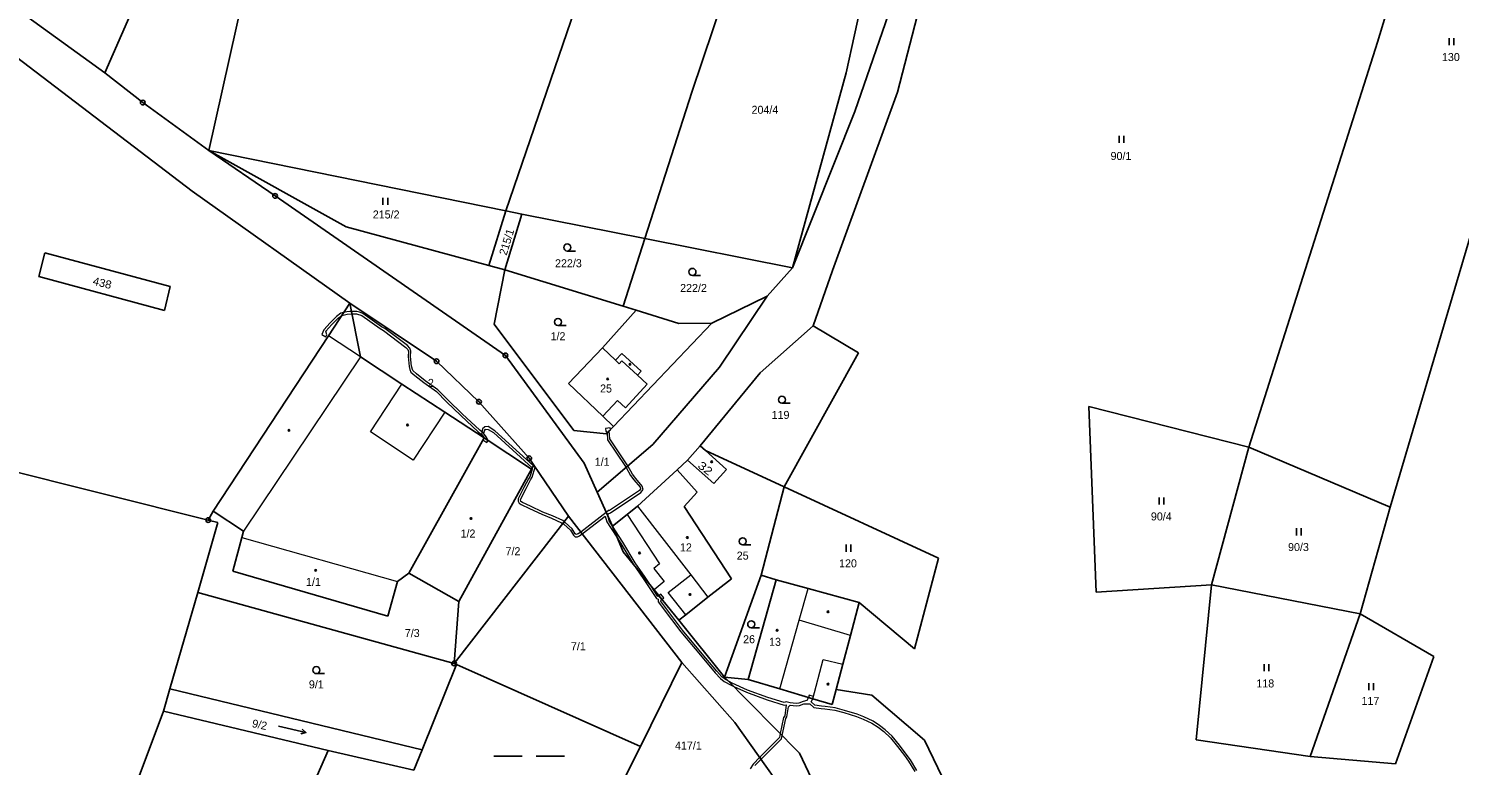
# Model space of a CAD drawing. Extents: x -791548 to -789311, y -1142631 to -1140855.
# Drawn here: x -790444.3 to -790140.3, y -1142115.7 to -1141959 of the extents above; entities that cross this region are included whole.
import ezdxf
from ezdxf.enums import TextEntityAlignment as Align

# ---------------------------------------------------------------- set-up
doc = ezdxf.new("R2010")
doc.units = 0
doc.header["$LTSCALE"] = 0.68
for name, color, linetype, lineweight in [('1', 7, 'Continuous', 25), ('13', 7, 'Continuous', 13), ('3', 7, 'Continuous', 25), ('4', 7, 'Continuous', 13), ('5', 7, 'Continuous', 25), ('8', 7, 'Continuous', 25)]:
    doc.layers.add(name, color=color, linetype=linetype, lineweight=lineweight)
doc.layers.add('2', color=7, linetype='Continuous')

msp = doc.modelspace()

# ---------------------------------------------------------------- linework, layer by layer
at = {"layer": '1'}
for p, q in [((-790157.72, -1141961.89), (-790134.26, -1141882.79)), ((-790342.92, -1141997.77), (-790319.97, -1141930.59)), ((-790303.39, -1141972.55), (-790290.79, -1141934.53)), ((-790268.79, -1141976.64), (-790254.81, -1141936.13)), ((-790250.25, -1141936.04), (-790259.72, -1141972.52)), ((-790428.12, -1141968.4), (-790469.57, -1141938.33)), ((-790264.99, -1141942.42), (-790270.6, -1141968.43)), ((-790417.13, -1141943.35), (-790428.12, -1141968.4)), ((-790465.97, -1141950.58), (-790409.55, -1141993.58)), ((-790398.03, -1141949.11), (-790406.03, -1141984.91)), ((-790185.09, -1142048.01), (-790157.72, -1141961.89)), ((-790420.07, -1141974.72), (-790428.12, -1141968.4)), ((-790270.6, -1141968.43), (-790282.03, -1142009.88)), ((-790313.39, -1142003.65), (-790303.39, -1141972.55)), ((-790259.72, -1141972.52), (-790273.56, -1142010.43)), ((-790155.05, -1142060.72), (-790128.27, -1141969.99)), ((-790406.03, -1141984.91), (-790420.07, -1141974.72)), ((-790282.03, -1142009.88), (-790268.79, -1141976.64)), ((-790376.88, -1142001.12), (-790406.03, -1141984.91)), ((-790406.03, -1141984.91), (-790342.92, -1141997.77)), ((-790406.03, -1141984.91), (-790391.97, -1141994.57)), ((-790409.55, -1141993.58), (-790376.08, -1142017.37)), ((-790391.97, -1141994.57), (-790343.02, -1142028.5)), ((-790346.58, -1142009.37), (-790342.92, -1141997.77)), ((-790343.18, -1142010.3), (-790339.54, -1141998.45)), ((-790342.92, -1141997.77), (-790339.54, -1141998.45)), ((-790339.54, -1141998.45), (-790313.39, -1142003.65)), ((-790346.58, -1142009.37), (-790376.88, -1142001.12)), ((-790318.01, -1142018.03), (-790313.39, -1142003.65)), ((-790313.39, -1142003.65), (-790282.03, -1142009.88)), ((-790442.18, -1142011.72), (-790440.91, -1142006.68)), ((-790440.91, -1142006.68), (-790414.25, -1142013.82)), ((-790415.48, -1142018.94), (-790442.18, -1142011.72)), ((-790343.18, -1142010.3), (-790346.58, -1142009.37)), ((-790345.39, -1142021.83), (-790343.18, -1142010.3)), ((-790343.18, -1142010.3), (-790318.01, -1142018.03)), ((-790282.03, -1142009.88), (-790287.44, -1142015.91)), ((-790273.56, -1142010.43), (-790277.66, -1142022.21)), ((-790414.25, -1142013.82), (-790415.48, -1142018.94)), ((-790380.63, -1142024.34), (-790376.08, -1142017.37)), ((-790376.08, -1142017.37), (-790357.66, -1142029.72)), ((-790373.78, -1142028.82), (-790376.08, -1142017.37)), ((-790318.01, -1142018.03), (-790315.23, -1142018.88)), ((-790287.44, -1142015.91), (-790299.16, -1142021.62)), ((-790297.55, -1142030.96), (-790287.44, -1142015.91)), ((-790322.41, -1142026.88), (-790315.23, -1142018.88)), ((-790315.23, -1142018.88), (-790306.18, -1142021.67)), ((-790405.11, -1142061.61), (-790380.63, -1142024.34)), ((-790345.39, -1142021.83), (-790328.52, -1142044.47)), ((-790320.06, -1142043.6), (-790299.16, -1142021.62)), ((-790306.18, -1142021.67), (-790299.16, -1142021.62)), ((-790277.66, -1142022.21), (-790288.91, -1142032.18)), ((-790277.66, -1142022.21), (-790268.01, -1142027.94)), ((-790329.64, -1142034.49), (-790322.41, -1142026.88)), ((-790365.01, -1142034.58), (-790373.78, -1142028.82)), ((-790357.66, -1142029.72), (-790348.64, -1142038.34)), ((-790343.02, -1142028.5), (-790326.31, -1142051.39)), ((-790268.01, -1142027.94), (-790283.8, -1142056.45)), ((-790311.67, -1142047.43), (-790297.55, -1142030.96)), ((-790288.91, -1142032.18), (-790301.63, -1142047.72)), ((-790355.91, -1142040.54), (-790365.01, -1142034.58)), ((-790329.64, -1142034.49), (-790322.34, -1142041.43)), ((-790348.64, -1142038.34), (-790337.96, -1142050.37)), ((-790185.09, -1142048.01), (-790219.05, -1142039.32)), ((-790219.05, -1142039.32), (-790217.5, -1142078.82)), ((-790347.56, -1142046.02), (-790355.91, -1142040.54)), ((-790322.34, -1142041.43), (-790320.06, -1142043.6)), ((-790328.52, -1142044.47), (-790321.58, -1142045.19)), ((-790321.58, -1142045.19), (-790320.06, -1142043.6)), ((-790406.17, -1142063.5), (-790476.62, -1142045.87)), ((-790363.53, -1142074.79), (-790347.56, -1142046.02)), ((-790337.45, -1142052.64), (-790347.56, -1142046.02)), ((-790323.55, -1142057.58), (-790311.67, -1142047.43)), ((-790301.63, -1142047.72), (-790304.34, -1142050.76)), ((-790301.63, -1142047.72), (-790300.49, -1142048.73)), ((-790283.8, -1142056.45), (-790300.49, -1142048.73)), ((-790300.49, -1142048.73), (-790296.03, -1142052.71)), ((-790185.09, -1142048.01), (-790192.99, -1142077.3)), ((-790155.05, -1142060.72), (-790185.09, -1142048.01)), ((-790337.96, -1142050.37), (-790337, -1142051.79)), ((-790337.45, -1142052.64), (-790337, -1142051.79)), ((-790337, -1142051.79), (-790329.59, -1142062.7)), ((-790326.31, -1142051.39), (-790323.55, -1142057.58)), ((-790304.34, -1142050.76), (-790306.55, -1142052.79)), ((-790298.74, -1142055.75), (-790304.34, -1142050.76)), ((-790352.9, -1142080.78), (-790337.45, -1142052.64)), ((-790306.55, -1142052.79), (-790314.98, -1142060.54)), ((-790306.55, -1142052.79), (-790302.31, -1142057.59)), ((-790296.03, -1142052.71), (-790298.74, -1142055.75)), ((-790320.28, -1142064.78), (-790323.55, -1142057.58)), ((-790302.31, -1142057.59), (-790305.03, -1142060.58)), ((-790288.68, -1142075.24), (-790283.8, -1142056.45)), ((-790283.8, -1142056.45), (-790251.02, -1142071.6)), ((-790314.98, -1142060.54), (-790317.17, -1142062.29)), ((-790305.03, -1142060.58), (-790295, -1142075.97)), ((-790161.45, -1142083.4), (-790155.05, -1142060.72)), ((-790408.39, -1142078.88), (-790404.1, -1142064.02)), ((-790405.11, -1142061.61), (-790406.17, -1142063.5)), ((-790404.1, -1142064.02), (-790406.17, -1142063.5)), ((-790405.11, -1142061.61), (-790398.66, -1142065.85)), ((-790329.59, -1142062.7), (-790353.92, -1142093.97)), ((-790305.56, -1142093.81), (-790329.59, -1142062.7)), ((-790317.17, -1142062.29), (-790320.28, -1142064.78)), ((-790399.03, -1142067.2), (-790398.66, -1142065.85)), ((-790320.28, -1142064.78), (-790318.01, -1142070.23)), ((-790400.97, -1142074.34), (-790399.03, -1142067.2)), ((-790318.01, -1142070.23), (-790311.41, -1142078.36)), ((-790251.02, -1142071.6), (-790256.08, -1142090.84)), ((-790368.04, -1142083.93), (-790400.97, -1142074.34)), ((-790365.96, -1142076.58), (-790363.53, -1142074.79)), ((-790363.53, -1142074.79), (-790352.9, -1142080.78)), ((-790295, -1142075.97), (-790299.99, -1142079.91)), ((-790296.46, -1142096.87), (-790288.68, -1142075.24)), ((-790291.44, -1142097.39), (-790285.47, -1142076.18)), ((-790285.47, -1142076.18), (-790288.68, -1142075.24)), ((-790278.72, -1142078.05), (-790285.47, -1142076.18)), ((-790414.31, -1142099.41), (-790408.39, -1142078.88)), ((-790353.92, -1142093.97), (-790408.39, -1142078.88)), ((-790368.04, -1142083.93), (-790365.96, -1142076.58)), ((-790311.41, -1142078.36), (-790306.19, -1142084.8)), ((-790267.86, -1142081.05), (-790278.72, -1142078.05)), ((-790217.5, -1142078.82), (-790192.99, -1142077.3)), ((-790192.99, -1142077.3), (-790196.24, -1142110.19)), ((-790161.45, -1142083.4), (-790192.99, -1142077.3)), ((-790352.9, -1142080.78), (-790353.92, -1142093.97)), ((-790299.99, -1142079.91), (-790304.7, -1142083.62)), ((-790269.7, -1142088.04), (-790267.86, -1142081.05)), ((-790256.08, -1142090.84), (-790267.86, -1142081.05)), ((-790304.7, -1142083.62), (-790306.19, -1142084.8)), ((-790306.19, -1142084.8), (-790296.46, -1142096.87)), ((-790161.45, -1142083.4), (-790172.03, -1142113.76)), ((-790145.76, -1142092.48), (-790161.45, -1142083.4)), ((-790271.32, -1142094.16), (-790269.7, -1142088.04)), ((-790360.74, -1142112.34), (-790353.43, -1142094.19)), ((-790353.92, -1142093.97), (-790353.43, -1142094.19)), ((-790353.43, -1142094.19), (-790314.29, -1142111.65)), ((-790314.29, -1142111.65), (-790305.56, -1142093.81)), ((-790294.25, -1142106.51), (-790305.56, -1142093.81)), ((-790272.73, -1142099.5), (-790271.32, -1142094.16)), ((-790153.93, -1142115.34), (-790145.76, -1142092.48)), ((-790296.46, -1142096.87), (-790280.51, -1142113.07)), ((-790296.46, -1142096.87), (-790291.44, -1142097.39)), ((-790291.44, -1142097.39), (-790284.71, -1142099.39)), ((-790415.68, -1142104.15), (-790414.31, -1142099.41)), ((-790414.31, -1142099.41), (-790360.74, -1142112.34)), ((-790284.71, -1142099.39), (-790277.7, -1142101.48)), ((-790273.57, -1142102.71), (-790272.73, -1142099.5)), ((-790265.16, -1142100.71), (-790272.73, -1142099.5)), ((-790277.7, -1142101.48), (-790273.57, -1142102.71)), ((-790253.96, -1142110.28), (-790265.16, -1142100.71)), ((-790415.68, -1142104.15), (-790447.27, -1142188.54)), ((-790380.65, -1142112.49), (-790415.68, -1142104.15)), ((-790284.19, -1142120.71), (-790294.25, -1142106.51)), ((-790390.45, -1142134.47), (-790380.65, -1142112.49)), ((-790380.65, -1142112.49), (-790362.5, -1142116.7)), ((-790362.5, -1142116.7), (-790360.74, -1142112.34)), ((-790330.46, -1142143.68), (-790314.29, -1142111.65)), ((-790248.33, -1142122.09), (-790253.96, -1142110.28)), ((-790196.24, -1142110.19), (-790172.03, -1142113.76)), ((-790280.51, -1142113.07), (-790273.1, -1142128.64)), ((-790172.03, -1142113.76), (-790153.93, -1142115.34))]:
    msp.add_line(p, q, dxfattribs=at)
at = {"layer": '13'}
for points in [[(-790381.17, -1142023.33), (-790379.88, -1142021.91), (-790378.59, -1142020.59), (-790377.8, -1142020), (-790377.4, -1142019.39), (-790378.02, -1142019.54), (-790378.93, -1142020.21), (-790380.24, -1142021.57), (-790381.61, -1142023.07), (-790382.06, -1142024.03), (-790381.2, -1142024.55), (-790380.94, -1142024.12)], [(-790376.74, -1142019.23), (-790377.4, -1142019.39), (-790377.8, -1142020), (-790376.64, -1142019.73), (-790375.63, -1142019.63), (-790375.73, -1142019.13), (-790376.05, -1142019.13)], [(-790375.73, -1142019.13), (-790375.63, -1142019.63), (-790374.66, -1142019.64), (-790373.53, -1142019.99), (-790369.6, -1142022.8), (-790368.95, -1142023.22), (-790364.18, -1142026.79), (-790363.77, -1142027.2), (-790363.64, -1142027.63), (-790363.69, -1142028.73), (-790363.46, -1142030.83), (-790363.3, -1142031.47), (-790363.09, -1142032.06), (-790362.25, -1142032.76), (-790360.37, -1142034.28), (-790357.67, -1142036.17), (-790355.52, -1142038.34), (-790352.52, -1142041.28), (-790348.79, -1142044.73), (-790348.04, -1142045.36), (-790347.56, -1142046.02), (-790346.74, -1142046.56), (-790347.04, -1142045.88), (-790347.68, -1142045.02), (-790348.45, -1142044.35), (-790352.18, -1142040.92), (-790355.16, -1142037.98), (-790357.35, -1142035.79), (-790360.07, -1142033.88), (-790361.93, -1142032.38), (-790362.69, -1142031.69), (-790362.96, -1142030.75), (-790363.19, -1142028.71), (-790363.14, -1142027.57), (-790363.33, -1142026.94), (-790363.84, -1142026.41), (-790368.67, -1142022.8), (-790369.32, -1142022.38), (-790373.29, -1142019.55), (-790374.02, -1142019.26), (-790374.6, -1142019.14)], [(-790347.43, -1142043.7), (-790347.92, -1142044.11), (-790348.13, -1142045.25), (-790347.56, -1142046.02), (-790346.69, -1142046.59), (-790347.04, -1142045.88), (-790347.59, -1142045.13), (-790347.48, -1142044.51), (-790347.23, -1142044.18), (-790346.71, -1142044.21), (-790345.56, -1142044.9), (-790337.33, -1142052.41), (-790337.08, -1142051.95), (-790345.26, -1142044.5), (-790346.69, -1142043.63)], [(-790321.42, -1142045.02), (-790320.95, -1142044.53), (-790320.72, -1142044.29), (-790320.8, -1142043.87), (-790321.79, -1142044.06), (-790321.69, -1142044.56)], [(-790321.42, -1142045.02), (-790321.34, -1142046.41), (-790317.5, -1142052.08), (-790317.38, -1142052.31), (-790316.46, -1142054.05), (-790315.73, -1142054.96), (-790314.42, -1142056.5), (-790314.31, -1142056.88), (-790314.56, -1142057.23), (-790320.89, -1142061.46), (-790321.1, -1142061.49), (-790321.6, -1142061.88), (-790321.19, -1142062.78), (-790321.18, -1142062.19), (-790320.71, -1142061.94), (-790314.22, -1142057.61), (-790313.75, -1142057.01), (-790313.96, -1142056.26), (-790315.35, -1142054.64), (-790316.04, -1142053.77), (-790316.98, -1142051.97), (-790320.84, -1142046.25), (-790320.95, -1142044.53)], [(-790346.69, -1142046.59), (-790346.74, -1142046.56), (-790347.56, -1142046.02), (-790347.8, -1142046.46), (-790346.97, -1142047)], [(-790337.08, -1142051.95), (-790337.33, -1142052.41), (-790337.36, -1142052.7), (-790337.8, -1142054.17), (-790338.15, -1142054.71), (-790339.09, -1142056.6), (-790340.32, -1142058.97), (-790340.32, -1142059.47), (-790340.12, -1142059.9), (-790339.66, -1142060.21), (-790337.91, -1142061.02), (-790335.26, -1142062.25), (-790333.24, -1142063.06), (-790331.1, -1142064.06), (-790330.81, -1142064.27), (-790330.5, -1142063.87), (-790330.84, -1142063.62), (-790333.04, -1142062.6), (-790335.06, -1142061.79), (-790337.69, -1142060.56), (-790339.42, -1142059.77), (-790339.72, -1142059.56), (-790339.82, -1142059.14), (-790338.65, -1142056.82), (-790337.71, -1142054.95), (-790337.34, -1142054.39), (-790336.71, -1142052.25)], [(-790330.5, -1142063.87), (-790330.81, -1142064.27), (-790330.64, -1142064.39), (-790329.21, -1142065.66), (-790328.55, -1142066.74), (-790328.19, -1142067.06), (-790327.7, -1142067.07), (-790327.29, -1142066.87), (-790326.71, -1142066.43), (-790327.01, -1142066.04), (-790327.55, -1142066.45), (-790327.99, -1142066.56), (-790328.17, -1142066.42), (-790328.83, -1142065.34), (-790330.32, -1142064.01)], [(-790321.6, -1142061.88), (-790327.01, -1142066.04), (-790326.71, -1142066.43), (-790321.82, -1142062.69), (-790321.45, -1142063.9), (-790320.7, -1142065.08), (-790319.21, -1142067.36), (-790320.28, -1142064.78), (-790320.99, -1142063.68), (-790321.19, -1142062.78)], [(-790315.44, -1142072.59), (-790318.07, -1142068.19), (-790320.28, -1142064.78), (-790319.21, -1142067.36), (-790318.49, -1142068.45), (-790315.81, -1142072.94), (-790312.09, -1142077.52), (-790313.35, -1142075.63)], [(-790315.81, -1142072.94), (-790313.77, -1142075.91), (-790310.94, -1142080.15), (-790310.54, -1142080.3), (-790310.56, -1142080.86), (-790307.73, -1142084.64), (-790305.77, -1142087.24), (-790301.61, -1142092.24), (-790298.45, -1142095.95), (-790297.35, -1142097.18), (-790296.53, -1142097.85), (-790295.06, -1142098.63), (-790294.46, -1142098.9), (-790295.52, -1142097.82), (-790296.25, -1142097.43), (-790297.01, -1142096.82), (-790298.07, -1142095.63), (-790301.23, -1142091.92), (-790305.37, -1142086.92), (-790307.33, -1142084.34), (-790310.06, -1142080.7), (-790309.78, -1142080.37), (-790310.41, -1142079.59), (-790310.62, -1142079.73), (-790312.09, -1142077.52)], [(-790310.02, -1142079.28), (-790310.41, -1142079.59), (-790309.78, -1142080.37), (-790309.39, -1142080.05)], [(-790278.52, -1142100.71), (-790278.66, -1142101.19), (-790277.7, -1142101.48), (-790277.57, -1142101)], [(-790284.21, -1142109.31), (-790284.64, -1142108.88), (-790284.8, -1142109.7), (-790288.99, -1142113.94), (-790288.69, -1142114.36), (-790284.35, -1142110)]]:
    msp.add_lwpolyline(points, close=True, dxfattribs=at)
for points in [[(-790255.61, -1142116.73), (-790256.95, -1142114.45), (-790257.85, -1142113.26), (-790259.29, -1142111.33), (-790260.88, -1142109.46), (-790262.32, -1142108.09), (-790263.56, -1142107.16), (-790264.91, -1142106.27), (-790266.84, -1142105.36), (-790268.27, -1142104.79), (-790271, -1142103.96), (-790272.96, -1142103.45), (-790275.07, -1142103.12), (-790275.85, -1142103.06), (-790277.29, -1142102.83), (-790278.08, -1142102.16), (-790277.7, -1142101.48), (-790278.66, -1142101.19), (-790278.95, -1142101.89), (-790279.73, -1142102.08), (-790280.66, -1142102.44), (-790281.24, -1142102.49), (-790282.54, -1142102.35), (-790283.34, -1142102.17), (-790283.82, -1142102.32), (-790287.24, -1142101.23), (-790291.61, -1142099.65), (-790294.84, -1142098.19), (-790295.52, -1142097.82), (-790294.46, -1142098.9), (-790291.79, -1142100.11), (-790287.4, -1142101.71), (-790283.82, -1142102.84), (-790283.36, -1142102.75), (-790283.68, -1142105.13), (-790283.92, -1142105.5), (-790284.64, -1142108.88), (-790284.21, -1142109.31), (-790283.44, -1142105.7), (-790283.2, -1142105.31), (-790282.91, -1142103.18), (-790282.53, -1142102.86), (-790281.24, -1142102.99), (-790280.54, -1142102.94), (-790279.59, -1142102.56), (-790278.37, -1142102.59), (-790277.48, -1142103.33), (-790275.91, -1142103.56), (-790275.13, -1142103.62), (-790273.06, -1142103.95), (-790271.14, -1142104.44), (-790268.43, -1142105.27), (-790267.04, -1142105.82), (-790265.15, -1142106.71), (-790263.84, -1142107.56), (-790262.64, -1142108.47), (-790261.24, -1142109.8), (-790259.69, -1142111.65), (-790258.25, -1142113.56), (-790257.37, -1142114.73), (-790256.05, -1142116.95)], [(-790290.02, -1142115.69), (-790288.69, -1142114.36), (-790288.99, -1142113.94), (-790290.42, -1142115.39), (-790291, -1142116.4)]]:
    msp.add_lwpolyline(points, dxfattribs=at)
at = {"layer": '3'}
for p, q in [((-790142.541, -1141962.53), (-790142.541, -1141961.03)), ((-790141.54, -1141962.53), (-790141.54, -1141961.03)), ((-790212.611, -1141983.32), (-790212.611, -1141981.82)), ((-790211.61, -1141983.32), (-790211.61, -1141981.82)), ((-790369.041, -1141996.45), (-790369.041, -1141994.95)), ((-790368.04, -1141996.45), (-790368.04, -1141994.95)), ((-790329.883, -1142006.29), (-790328.133, -1142006.29)), ((-790303.293, -1142011.48), (-790301.543, -1142011.48)), ((-790331.843, -1142022.13), (-790330.093, -1142022.13)), ((-790284.273, -1142038.66), (-790282.523, -1142038.66)), ((-790204.161, -1142060.19), (-790204.161, -1142058.69)), ((-790203.16, -1142060.19), (-790203.16, -1142058.69)), ((-790174.951, -1142066.75), (-790174.951, -1142065.25)), ((-790173.95, -1142066.75), (-790173.95, -1142065.25)), ((-790292.603, -1142068.77), (-790290.853, -1142068.77)), ((-790270.641, -1142070.22), (-790270.641, -1142068.72)), ((-790269.64, -1142070.22), (-790269.64, -1142068.72)), ((-790290.793, -1142086.4), (-790289.043, -1142086.4)), ((-790181.821, -1142095.64), (-790181.821, -1142094.14)), ((-790180.82, -1142095.64), (-790180.82, -1142094.14)), ((-790383.193, -1142096.15), (-790381.443, -1142096.15)), ((-790159.611, -1142099.64), (-790159.611, -1142098.14)), ((-790158.61, -1142099.64), (-790158.61, -1142098.14)), ((-790385.402, -1142108.647), (-790386.467, -1142108.916)), ((-790345.489, -1142113.71), (-790339.489, -1142113.71)), ((-790336.489, -1142113.71), (-790330.489, -1142113.71))]:
    msp.add_line(p, q, dxfattribs=at)
msp.add_lwpolyline([(-790391.248, -1142107.297), (-790385.402, -1142108.647), (-790386.241, -1142107.939)], dxfattribs=at)
for centre in [(-790329.8829, -1142005.5398), (-790303.2929, -1142010.7298), (-790331.8429, -1142021.3798), (-790284.2729, -1142037.9098), (-790292.6029, -1142068.0198), (-790290.7929, -1142085.6498), (-790383.1929, -1142095.3998)]:
    msp.add_circle(centre, 0.75, dxfattribs=at)
at = {"layer": '4'}
for p, q in [((-790373.78, -1142028.82), (-790380.63, -1142024.34)), ((-790322.41, -1142026.88), (-790319.65, -1142029.5)), ((-790373.78, -1142028.82), (-790398.66, -1142065.85)), ((-790319.65, -1142029.5), (-790318.27, -1142028.05)), ((-790319.65, -1142029.5), (-790318.83, -1142030.26)), ((-790318.83, -1142030.26), (-790318.29, -1142029.67)), ((-790318.29, -1142029.67), (-790314.98, -1142032.72)), ((-790318.27, -1142028.05), (-790314.17, -1142031.84)), ((-790314.17, -1142031.84), (-790314.98, -1142032.72)), ((-790314.98, -1142032.72), (-790312.92, -1142034.62)), ((-790371.69, -1142044.77), (-790365.01, -1142034.58)), ((-790312.92, -1142034.62), (-790317.53, -1142039.62)), ((-790322.34, -1142041.43), (-790319.22, -1142038.06)), ((-790319.22, -1142038.06), (-790317.53, -1142039.62)), ((-790355.91, -1142040.54), (-790362.59, -1142050.73)), ((-790362.59, -1142050.73), (-790371.69, -1142044.77)), ((-790314.98, -1142060.54), (-790303.66, -1142075.16)), ((-790317.17, -1142062.29), (-790310.31, -1142072.82)), ((-790399.03, -1142067.2), (-790365.96, -1142076.58)), ((-790310.31, -1142072.82), (-790311.47, -1142073.78)), ((-790311.47, -1142073.78), (-790309.32, -1142076.55)), ((-790308.42, -1142078.91), (-790303.66, -1142075.16)), ((-790303.66, -1142075.16), (-790299.99, -1142079.91)), ((-790309.32, -1142076.55), (-790311.41, -1142078.36)), ((-790304.7, -1142083.62), (-790308.42, -1142078.91)), ((-790284.71, -1142099.39), (-790280.61, -1142084.79)), ((-790277.7, -1142101.48), (-790275.49, -1142093.11)), ((-790275.49, -1142093.11), (-790271.32, -1142094.16))]:
    msp.add_line(p, q, dxfattribs=at)
msp.add_lwpolyline([(-790269.7, -1142088.04), (-790280.61, -1142084.79), (-790278.72, -1142078.05)], dxfattribs=at)
at = {"layer": '5'}
for centre in [(-790316.5488, -1142030.3733), (-790321.2888, -1142033.4933), (-790388.9888, -1142044.4033), (-790363.8188, -1142043.2733), (-790299.2088, -1142051.1033), (-790350.3388, -1142063.1633), (-790304.3788, -1142067.2133), (-790314.5188, -1142070.4833), (-790383.3488, -1142074.1933), (-790303.7988, -1142079.3233), (-790274.4988, -1142083.0033), (-790285.2988, -1142086.9233), (-790274.4988, -1142098.3733)]:
    msp.add_circle(centre, 0.175, dxfattribs=at)
at = {"layer": '8'}
for centre, radius in [((-790420.0699, -1141974.72), 0.5), ((-790420.0699, -1141974.72), 0.0303), ((-790391.9699, -1141994.57), 0.5), ((-790391.9699, -1141994.57), 0.0303), ((-790357.6599, -1142029.72), 0.5), ((-790357.6599, -1142029.72), 0.0303), ((-790343.0199, -1142028.5), 0.5), ((-790343.0199, -1142028.5), 0.0303), ((-790348.6399, -1142038.34), 0.5), ((-790348.6399, -1142038.34), 0.0303), ((-790337.9599, -1142050.37), 0.5), ((-790337.9599, -1142050.37), 0.0303), ((-790406.17, -1142063.4999), 0.5), ((-790406.17, -1142063.4999), 0.0303), ((-790353.9199, -1142093.97), 0.5), ((-790353.9199, -1142093.97), 0.0303)]:
    msp.add_circle(centre, radius, dxfattribs=at)

# ---------------------------------------------------------------- texts
at = {"layer": '2'}
for s, p in [('130', (-790142.149, -1141965.902)), ('204/4', (-790287.89, -1141977.112)), ('90/1', (-790212.239, -1141986.932)), ('215/2', (-790368.36, -1141999.372)), ('222/3', (-790329.64, -1142009.742)), ('222/2', (-790303.06, -1142015.002)), ('1/2', (-790331.85, -1142025.262)), ('2', (-790358.86, -1142035.182)), ('25', (-790321.649, -1142036.372)), ('119', (-790284.569, -1142041.992)), ('1/1', (-790322.47, -1142051.962)), ('90/4', (-790203.669, -1142063.572)), ('1/2', (-790350.98, -1142067.212)), ('7/2', (-790341.42, -1142070.972)), ('12', (-790304.679, -1142070.152)), ('90/3', (-790174.529, -1142070.082)), ('25', (-790292.609, -1142071.902)), ('120', (-790270.239, -1142073.552)), ('1/1', (-790383.81, -1142077.482)), ('7/3', (-790362.82, -1142088.372)), ('26', (-790291.259, -1142089.685)), ('7/1', (-790327.53, -1142091.182)), ('13', (-790285.749, -1142090.232)), ('118', (-790181.579, -1142099.082)), ('9/1', (-790383.2, -1142099.282)), ('117', (-790159.239, -1142102.792)), ('417/1', (-790304.15, -1142112.292))]:
    msp.add_text(s, height=1.7, dxfattribs=at).set_placement(p, align=Align.CENTER)
for s, rotation, p in [('215/1', 73, (-790341.9542, -1142004.6285)), ('9/2', 348, (-790395.4257, -1142107.8237))]:
    msp.add_text(s, height=1.7, rotation=rotation, dxfattribs=at).set_placement(p, align=Align.CENTER)
for s, rotation, width, p in [('438', 346, 1.05, (-790428.8756, -1142013.9005)), ('32', 322, 1.25, (-790301.0733, -1142053.1582))]:
    msp.add_text(s, height=1.7, rotation=rotation, dxfattribs=dict(at, width=width)).set_placement(p, align=Align.CENTER)

doc.saveas('drawing.dxf')
